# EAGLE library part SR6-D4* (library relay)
Safety Relay 4 pole 8 A SCHRACK 2 N/O contact and 2 N/C contact Source: http://www.schrack.com/.. 5814.pdf
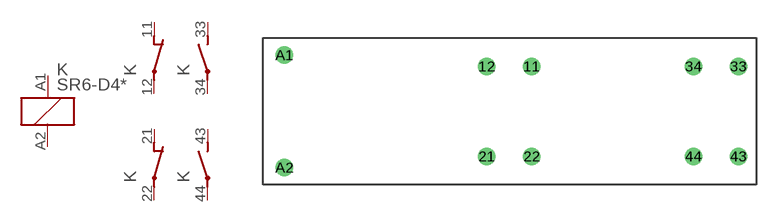
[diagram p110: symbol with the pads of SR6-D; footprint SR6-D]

Designator prefix K; gates 1=K 2=O 3=O 4=S 5=S

## SR6-D4005 (OC_FARNELL: unknown; OC_NEWARK: unknown), SR6-D4006 (OC_FARNELL: unknown; OC_NEWARK: unknown), SR6-D4009 (OC_FARNELL: unknown; OC_NEWARK: unknown), SR6-D4012 (MPN: SR6D4012; OC_FARNELL: 1770622; OC_NEWARK: 51R7440), SR6-D4018 (OC_FARNELL: unknown; OC_NEWARK: unknown), SR6-D4021 (OC_FARNELL: unknown; OC_NEWARK: unknown), SR6-D4024 (MPN: SR6D4024; OC_FARNELL: 1770623; OC_NEWARK: 51R7441), SR6-D4036 (OC_FARNELL: unknown; OC_NEWARK: unknown), SR6-D4040 (OC_FARNELL: unknown; OC_NEWARK: unknown), SR6-D4048 (OC_FARNELL: unknown; OC_NEWARK: unknown), SR6-D4060 (OC_FARNELL: unknown; OC_NEWARK: unknown), SR6-D4085 (OC_FARNELL: unknown; OC_NEWARK: unknown), SR6-D4110 (MPN: SR6D4110; OC_FARNELL: unknown; OC_NEWARK: 16R7721)  [SR6-D]
11  2:O  pas
12  2:P  pas
21  3:O  pas
22  3:P  pas
33  4:S  pas
34  4:P  pas
43  5:S  pas
44  5:P  pas
A1  1:1  pas
A2  1:2  pas

## Footprint SR6-D (pad centres in mm)
Safety Relay 4 pole 8 A SCHRACK 2 N/O contact and 2 N/C contact Source: http://www.schrack.com/.. 5814.pdf
drill 1.3 round: 11 2.5,5; 12 -2.5,5; 21 -2.5,-5; 22 2.5,-5; 33 25.5,5; 34 20.5,5; 43 25.5,-5; 44 20.5,-5; A1 -25,6.25; A2 -25,-6.25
